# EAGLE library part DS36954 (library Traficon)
Quad RS485 bus transceiver
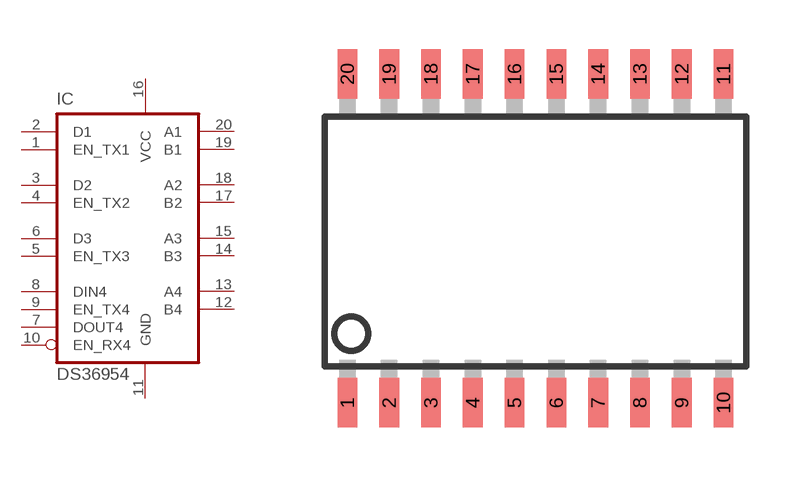
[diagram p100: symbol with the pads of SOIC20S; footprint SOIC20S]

Designator prefix IC

## DS36954  [SOIC20S]
1  EN_TX1
2  D1
3  D2
4  EN_TX2
5  EN_TX3
6  D3
7  DOUT4
8  DIN4
9  EN_TX4
10  EN_RX4
11  GND
12  B4
13  A4
14  B3
15  A3
16  VCC
17  B2
18  A2
19  B1
20  A1

## Footprint SOIC20S (pad centres in mm)
Wide Plastic Gull Wing Small Outline Package
smd 0.6 x 1.5: 1 -5.715,-5; 2 -4.445,-5; 3 -3.175,-5; 4 -1.905,-5; 5 -0.635,-5; 6 0.635,-5; 7 1.905,-5; 8 3.175,-5; 9 4.445,-5; 10 5.715,-5; 11 5.715,5; 12 4.445,5; 13 3.175,5; 14 1.905,5; 15 0.635,5; 16 -0.635,5; 17 -1.905,5; 18 -3.175,5; 19 -4.445,5; 20 -5.715,5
